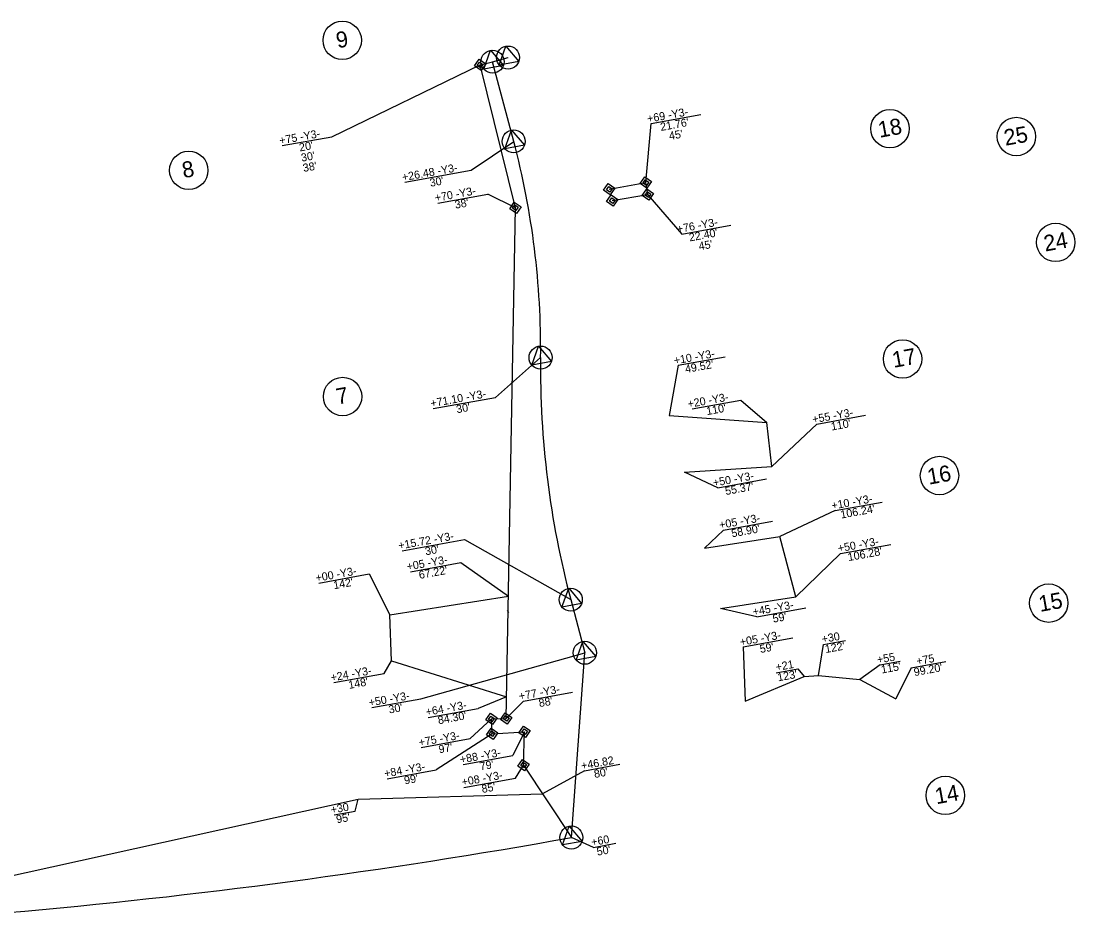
# Model space of a CAD drawing. Extents: x 1618217 to 1621927, y 897445 to 899141.
# Drawn here: x 1620531 to 1621189, y 898096 to 898663 of the extents above; entities that cross this region are included whole.
import ezdxf

# ---------------------------------------------------------------- set-up
doc = ezdxf.new("R2010")
doc.units = 0
for name, color, linetype in [('Prop Easement Construction', 7, 'Continuous'), ('Prop Easement Construction Station Offsets', 7, 'Continuous'), ('Prop Easement Permanent Utility', 7, 'Continuous'), ('Prop Easement Permanent Utility Station Offsets', 7, 'Continuous'), ('Prop Parcel Number CELL', 7, 'Continuous'), ('Prop ROW Marker CELL', 7, 'Continuous'), ('Prop ROW Permanent Easement CELL', 7, 'Continuous'), ('Prop ROW RW Lines', 7, 'Continuous'), ('Prop ROW Station Offsets', 7, 'Continuous')]:
    doc.layers.add(name, color=color, linetype=linetype)

msp = doc.modelspace()

# ---------------------------------------------------------------- linework, layer by layer
at = {"layer": 'Prop Easement Construction'}
for p, q in [((1620935.63, 898416.66), (1620996.55, 898412.44)), ((1620999.68, 898384.84), (1620996.55, 898412.44)), ((1620945, 898381.35), (1620999.68, 898384.84)), ((1620957.63, 898333.79), (1621004.58, 898341.14)), ((1621014.58, 898303.59), (1621004.58, 898341.14)), ((1620760.99, 898292.3), (1620835.11, 898303.88)), ((1620967.6, 898296.28), (1621014.58, 898303.59)), ((1620835.36, 898293.41), (1620834.61, 898294.98)), ((1620762.14, 898263.44), (1620760.99, 898292.3)), ((1620762.14, 898263.44), (1620833.98, 898241.13)), ((1620982.99, 898238.29), (1621019.79, 898253.72)), ((1621019.79, 898253.72), (1621028.82, 898254.34)), ((1621028.82, 898254.34), (1621054.67, 898251.9)), ((1621054.67, 898251.9), (1621077.16, 898239.91)), ((1620374.41, 898096.16), (1620741.24, 898177.16)), ((1620741.24, 898177.16), (1620856.43, 898180.5))]:
    msp.add_line(p, q, dxfattribs=at)
at = {"layer": 'Prop Easement Construction Station Offsets'}
for p, q in [((1620941.05, 898448.07), (1620970.58, 898453.42)), ((1620941.05, 898448.07), (1620935.63, 898416.66)), ((1620949.87, 898420.86), (1620980.29, 898426.37)), ((1620980.29, 898426.37), (1620996.55, 898412.44)), ((1621027.78, 898411.4), (1621058.08, 898416.89)), ((1621027.78, 898411.4), (1620999.68, 898384.84)), ((1620965.84, 898371.56), (1620945, 898381.35)), ((1620965.84, 898371.56), (1620996.27, 898377.07)), ((1621039.23, 898357.33), (1621068.62, 898362.65)), ((1621039.23, 898357.33), (1621004.58, 898341.14)), ((1620969.37, 898345.16), (1621000.14, 898350.73)), ((1620969.37, 898345.16), (1620957.63, 898333.79)), ((1621042.63, 898330.47), (1621074, 898336.14)), ((1621042.63, 898330.47), (1621014.58, 898303.59)), ((1620773.9, 898319.19), (1620805.48, 898324.91)), ((1620805.48, 898324.91), (1620835.11, 898303.88)), ((1620716.69, 898312.06), (1620748.26, 898317.78)), ((1620748.26, 898317.78), (1620760.99, 898292.3)), ((1620990.21, 898291.1), (1620967.6, 898296.28)), ((1620990.21, 898291.1), (1621020.9, 898296.66)), ((1620981.75, 898272.25), (1621012.74, 898277.86)), ((1621031.9, 898273.78), (1621045.75, 898276.29)), ((1620981.75, 898272.25), (1620982.99, 898238.29)), ((1621028.82, 898254.34), (1621031.9, 898273.78)), ((1620757.46, 898255.57), (1620762.14, 898263.44)), ((1621067.31, 898261.06), (1621079.77, 898263.32)), ((1621086.7, 898259.15), (1621108.39, 898263.08)), ((1620726.19, 898249.91), (1620757.46, 898255.57)), ((1621002.32, 898256.06), (1621015.97, 898258.53)), ((1621015.97, 898258.53), (1621019.79, 898253.72)), ((1621067.31, 898261.06), (1621054.67, 898251.9)), ((1621086.7, 898259.15), (1621077.16, 898239.91)), ((1620833.98, 898241.13), (1620816.27, 898233.71)), ((1620785.05, 898228.06), (1620816.27, 898233.71)), ((1620882.69, 898194.94), (1620904.81, 898198.94)), ((1620882.69, 898194.94), (1620856.43, 898180.5)), ((1620739.46, 898169.75), (1620741.24, 898177.16)), ((1620726.36, 898167.38), (1620739.46, 898169.75))]:
    msp.add_line(p, q, dxfattribs=at)
at = {"layer": 'Prop Easement Permanent Utility'}
for p, q in [((1620817.48, 898635.58), (1620825.21, 898637.63)), ((1620839.46, 898546.38), (1620817.48, 898635.58)), ((1620898.1, 898557.98), (1620920.96, 898562.14)), ((1620922.27, 898554.66), (1620920.96, 898562.14)), ((1620899.97, 898550.91), (1620922.27, 898554.66)), ((1620833.74, 898227.62), (1620839.46, 898546.38)), ((1620824.52, 898227.24), (1620833.74, 898227.62)), ((1620824.9, 898218.03), (1620824.52, 898227.24)), ((1620824.9, 898218.03), (1620845.26, 898219.3)), ((1620844.59, 898198.43), (1620845.26, 898219.3)), ((1620844.59, 898198.43), (1620874.45, 898153.23))]:
    msp.add_line(p, q, dxfattribs=at)
at = {"layer": 'Prop Easement Permanent Utility Station Offsets'}
for p, q in [((1620924.35, 898599.12), (1620955.22, 898604.71)), ((1620920.96, 898562.14), (1620924.35, 898599.12)), ((1620791.13, 898549.32), (1620822.38, 898554.97)), ((1620839.46, 898546.38), (1620822.38, 898554.97)), ((1620922.23, 898554.52), (1620943.52, 898529.99)), ((1620943.52, 898529.99), (1620974.13, 898535.53)), ((1620844.66, 898238.35), (1620875.14, 898243.87)), ((1620833.74, 898227.62), (1620844.66, 898238.35)), ((1620824.52, 898227.24), (1620811.34, 898214.97)), ((1620824.9, 898218.03), (1620790.09, 898195.43)), ((1620845.26, 898219.3), (1620837.98, 898204.53)), ((1620780.67, 898209.42), (1620811.34, 898214.97)), ((1620806.93, 898198.91), (1620837.98, 898204.53)), ((1620759.34, 898189.87), (1620790.09, 898195.43)), ((1620839.52, 898190.37), (1620844.59, 898198.43)), ((1620807.34, 898184.55), (1620839.52, 898190.37))]:
    msp.add_line(p, q, dxfattribs=at)
at = {"layer": 'Prop Parcel Number CELL'}
for p, q in [((1620731.35, 898650.97), (1620731.35, 898650.97)), ((1621073.44, 898595.8), (1621073.44, 898595.8)), ((1621152.38, 898590.89), (1621152.38, 898590.89)), ((1620635.51, 898569.78), (1620635.51, 898569.78)), ((1621176.93, 898524.79), (1621176.93, 898524.79)), ((1621081.3, 898452), (1621081.3, 898452)), ((1620731.58, 898428.55), (1620731.58, 898428.55)), ((1621104.35, 898379.22), (1621104.35, 898379.22)), ((1621172.57, 898299.57), (1621172.57, 898299.57)), ((1621107.99, 898179.52), (1621107.99, 898179.52))]:
    msp.add_line(p, q, dxfattribs=at)
for centre in [(1620731.35, 898650.97), (1621073.44, 898595.8), (1621152.38, 898590.89), (1620635.51, 898569.78), (1621176.93, 898524.79), (1621081.3, 898452), (1620731.58, 898428.55), (1621104.35, 898379.22), (1621172.57, 898299.57), (1621107.99, 898179.52)]:
    msp.add_circle(centre, 12, dxfattribs=at)
at = {"layer": 'Prop ROW Marker CELL'}
for p, q in [((1620825.21, 898637.63), (1620825.21, 898637.63)), ((1620834.88, 898640.2), (1620834.88, 898640.2)), ((1620817.48, 898635.58), (1620817.48, 898635.58)), ((1620838.42, 898587.88), (1620838.42, 898587.88)), ((1620898.1, 898557.98), (1620898.1, 898557.98)), ((1620920.96, 898562.14), (1620920.96, 898562.14)), ((1620899.97, 898550.91), (1620899.97, 898550.91)), ((1620922.27, 898554.66), (1620922.27, 898554.66)), ((1620839.46, 898546.38), (1620839.46, 898546.38)), ((1620855.24, 898452.86), (1620855.24, 898452.86)), ((1620874.06, 898301.73), (1620874.06, 898301.73)), ((1620882.86, 898268.6), (1620882.86, 898268.6)), ((1620824.52, 898227.24), (1620824.52, 898227.24)), ((1620833.74, 898227.62), (1620833.74, 898227.62)), ((1620824.9, 898218.03), (1620824.9, 898218.03)), ((1620845.26, 898219.3), (1620845.26, 898219.3)), ((1620844.59, 898198.43), (1620844.59, 898198.43)), ((1620874.45, 898153.23), (1620874.45, 898153.23))]:
    msp.add_line(p, q, dxfattribs=at)
for points in [[(1620819.7, 898632.98), (1620823.93, 898644.72), (1620832, 898635.2)], [(1620829.37, 898635.54), (1620833.59, 898647.28), (1620841.67, 898637.77)], [(1620832.92, 898583.22), (1620837.14, 898594.96), (1620845.22, 898585.45)], [(1620849.73, 898448.2), (1620853.96, 898459.94), (1620862.03, 898450.43)], [(1620868.55, 898297.08), (1620872.78, 898308.82), (1620880.85, 898299.3)], [(1620877.35, 898263.95), (1620881.58, 898275.69), (1620889.65, 898266.17)], [(1620868.94, 898148.57), (1620873.16, 898160.31), (1620881.24, 898150.8)]]:
    msp.add_lwpolyline(points, close=True, dxfattribs=at)
for centre in [(1620825.21, 898637.63), (1620834.88, 898640.2), (1620838.42, 898587.88), (1620855.24, 898452.86), (1620874.06, 898301.73), (1620882.86, 898268.6), (1620874.45, 898153.23)]:
    msp.add_circle(centre, 7.2, dxfattribs=at)
at = {"layer": 'Prop ROW Permanent Easement CELL'}
for points in [[(1620816.84, 898639.12), (1620821.02, 898636.22), (1620818.12, 898632.04), (1620813.94, 898634.94)], [(1620817.16, 898637.35), (1620819.25, 898635.9), (1620817.8, 898633.81), (1620815.71, 898635.26)], [(1620920.32, 898565.68), (1620924.5, 898562.78), (1620921.6, 898558.6), (1620917.42, 898561.5)], [(1620920.64, 898563.91), (1620922.73, 898562.46), (1620921.28, 898560.37), (1620919.19, 898561.82)], [(1620897.46, 898561.52), (1620901.64, 898558.62), (1620898.74, 898554.44), (1620894.55, 898557.34)], [(1620897.78, 898559.75), (1620899.87, 898558.3), (1620898.42, 898556.21), (1620896.33, 898557.66)], [(1620921.63, 898558.2), (1620925.81, 898555.3), (1620922.91, 898551.12), (1620918.72, 898554.02)], [(1620899.33, 898554.45), (1620903.52, 898551.55), (1620900.62, 898547.37), (1620896.43, 898550.27)], [(1620899.65, 898552.68), (1620901.75, 898551.23), (1620900.3, 898549.14), (1620898.2, 898550.59)], [(1620921.95, 898556.43), (1620924.04, 898554.98), (1620922.59, 898552.89), (1620920.5, 898554.34)], [(1620838.82, 898549.92), (1620843, 898547.02), (1620840.1, 898542.84), (1620835.92, 898545.74)], [(1620839.14, 898548.15), (1620841.23, 898546.7), (1620839.78, 898544.61), (1620837.69, 898546.06)], [(1620823.88, 898230.78), (1620828.07, 898227.88), (1620825.16, 898223.7), (1620820.98, 898226.6)], [(1620824.2, 898229.01), (1620826.29, 898227.56), (1620824.84, 898225.47), (1620822.75, 898226.92)], [(1620833.09, 898231.16), (1620837.28, 898228.26), (1620834.38, 898224.08), (1620830.19, 898226.98)], [(1620833.41, 898229.39), (1620835.51, 898227.94), (1620834.06, 898225.85), (1620831.96, 898227.3)], [(1620844.62, 898222.84), (1620848.8, 898219.94), (1620845.9, 898215.76), (1620841.71, 898218.66)], [(1620824.26, 898221.57), (1620828.44, 898218.67), (1620825.54, 898214.49), (1620821.36, 898217.39)], [(1620824.58, 898219.8), (1620826.67, 898218.35), (1620825.22, 898216.26), (1620823.13, 898217.71)], [(1620844.94, 898221.07), (1620847.03, 898219.62), (1620845.58, 898217.53), (1620843.49, 898218.98)], [(1620843.95, 898201.97), (1620848.13, 898199.07), (1620845.23, 898194.89), (1620841.05, 898197.79)], [(1620844.27, 898200.2), (1620846.36, 898198.75), (1620844.91, 898196.66), (1620842.82, 898198.11)]]:
    msp.add_lwpolyline(points, close=True, dxfattribs=at)
at = {"layer": 'Prop ROW RW Lines'}
for p, q in [((1620825.21, 898637.63), (1620834.88, 898640.2)), ((1620838.42, 898587.88), (1620825.21, 898637.63)), ((1620874.06, 898301.73), (1620882.86, 898268.6)), ((1620874.45, 898153.23), (1620882.86, 898268.6))]:
    msp.add_line(p, q, dxfattribs=at)
for centre, radius, start, end in [((1620352.28, 898458.77), 503, 359.3265, 14.87271), ((1621418.2, 898446.24), 563, 179.3265, 194.87271), ((1620177.4, 902041.24), 3950, 275.00553, 280.16405)]:
    msp.add_arc(centre, radius, start, end, dxfattribs=at)
at = {"layer": 'Prop ROW Station Offsets'}
for p, q in [((1620724.78, 898590.79), (1620817.48, 898635.58)), ((1620693.85, 898585.19), (1620724.78, 898590.79)), ((1620811.79, 898569.79), (1620838.42, 898587.88)), ((1620770.42, 898562.31), (1620811.79, 898569.79)), ((1620826.99, 898428.01), (1620855.24, 898452.86)), ((1620788.18, 898420.99), (1620826.99, 898428.01)), ((1620768.82, 898332.3), (1620807.71, 898339.34)), ((1620807.71, 898339.34), (1620874.06, 898301.73)), ((1620780.46, 898239.85), (1620882.86, 898268.6)), ((1620749.88, 898234.32), (1620780.46, 898239.85)), ((1620888.31, 898147.08), (1620874.45, 898153.23)), ((1620888.31, 898147.08), (1620902.23, 898149.6))]:
    msp.add_line(p, q, dxfattribs=at)

# ---------------------------------------------------------------- texts
at = {"layer": 'Prop Easement Construction Station Offsets'}
for s, p in [('+10 -Y3-', (1620938.92, 898448.55)), ("49.52'", (1620945.9, 898443.21)), ('+20 -Y3-', (1620947.52, 898421.42)), ("110'", (1620959.17, 898416.93)), ('+55 -Y3-', (1621025.38, 898411.8)), ("110'", (1621037.04, 898407.31)), ('+50 -Y3-', (1620963.36, 898372.24)), ("55.37'", (1620970.92, 898367.01)), ('+10 -Y3-', (1621037.35, 898357.92)), ("106.24'", (1621042.96, 898352.33)), ('+05 -Y3-', (1620967.25, 898345.86)), ("58.90'", (1620974.81, 898340.62)), ('+50 -Y3-', (1621041.33, 898331.28)), ("106.28'", (1621047.53, 898325.79)), ('+05 -Y3-', (1620772.08, 898319.89)), ('+00 -Y3-', (1620715.19, 898312.81)), ("67.22'", (1620779.64, 898314.65)), ("142'", (1620726.26, 898308.21)), ('+45 -Y3-', (1620988.17, 898291.68)), ("59'", (1621000.59, 898287.33)), ('+05 -Y3-', (1620980.16, 898272.78)), ('+30', (1621031.28, 898274.62)), ("59'", (1620992.59, 898268.42)), ("122'", (1621033.33, 898268.39)), ('+55', (1621065.79, 898261.74)), ('+21', (1621002.52, 898257.13)), ("115'", (1621068.33, 898255.6)), ("99.20'", (1621088.8, 898253.96)), ('+75', (1621090.36, 898260.85)), ('+24 -Y3-', (1620724.58, 898250.59)), ("123'", (1621003.59, 898250.72)), ("148'", (1620735.65, 898245.99)), ('+64 -Y3-', (1620783.97, 898229.14)), ("84.30'", (1620791.53, 898223.91)), ('+46.82', (1620881.03, 898195.54)), ("80'", (1620889.03, 898190.38)), ('+30', (1620724.66, 898168.05)), ("95'", (1620728.06, 898162.06))]:
    msp.add_text(s, height=5, rotation=10.25995, dxfattribs=at).set_placement(p)
at = {"layer": 'Prop Easement Permanent Utility Station Offsets'}
for s, p in [('+69 -Y3-', (1620922.27, 898599.48)), ("21.76'", (1620930.42, 898594.35)), ("45'", (1620935.86, 898588.73)), ('+70 -Y3-', (1620789.66, 898550.15)), ("38'", (1620802.08, 898545.8)), ('+76 -Y3-', (1620940.81, 898530.61)), ("22.40'", (1620948.37, 898525.37)), ("45' ", (1620954.39, 898519.86)), ('+77 -Y3-', (1620842.12, 898239)), ("88'", (1620854.54, 898234.65)), ('+75 -Y3-', (1620779.57, 898210.13)), ("97'", (1620792, 898205.77)), ('+88 -Y3-', (1620805.3, 898199.45)), ('+84 -Y3-', (1620758.05, 898190.69)), ("79' ", (1620817.72, 898195.09)), ("99'", (1620770.48, 898186.33)), ('+08 -Y3-', (1620806.42, 898185.37)), ("85' ", (1620818.84, 898181.02))]:
    msp.add_text(s, height=5, rotation=10.2583, dxfattribs=at).set_placement(p)
at = {"layer": 'Prop Parcel Number CELL'}
for s, p in [('9', (1620728.45, 898645.97)), ('18', (1621066.91, 898590.08)), ('25', (1621145.56, 898585.11)), ('8', (1620632.25, 898564.87)), ('24', (1621170.4, 898519.06)), ('17', (1621075.74, 898446.45)), ('7', (1620728.47, 898423.51)), ('16', (1621097.68, 898373.48)), ('15', (1621167.22, 898294.06)), ('14', (1621102.44, 898173.97))]:
    msp.add_text(s, height=10, rotation=10.2583, dxfattribs=at).set_placement(p)
at = {"layer": 'Prop ROW Station Offsets'}
for s, p in [('+75 -Y3-', (1620692.5, 898585.9)), ("20'", (1620704.93, 898581.55)), ("30'", (1620706.09, 898575.15)), ("38'", (1620707.24, 898568.75)), ('+26.48 -Y3-', (1620769.16, 898562.95)), ("30'", (1620786.45, 898559.47)), ('+71.10 -Y3-', (1620786.92, 898421.79)), ("30'", (1620803.03, 898418.1)), ('+15.72 -Y3-', (1620766.83, 898332.99)), ("30'", (1620783.53, 898329.41)), ('+50 -Y3-', (1620748.36, 898234.98)), ("30' ", (1620760.78, 898230.62)), ('+60', (1620887.33, 898147.87)), ("50'", (1620890.74, 898141.88))]:
    msp.add_text(s, height=5, rotation=10.2583, dxfattribs=at).set_placement(p)

doc.saveas('drawing.dxf')
